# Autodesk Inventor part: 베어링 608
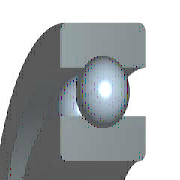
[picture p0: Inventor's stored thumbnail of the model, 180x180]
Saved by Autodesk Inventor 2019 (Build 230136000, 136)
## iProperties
IsCustomPart: 1
Created: 2012-02
Part Number: 베어링 608
Material: 강철, 연강
Description: 깊은 그루브 볼 베어링
Document SubType Name: Modeling
Standard: KS B 2023
Designer: mduedu
Standards Organization: KS
Language: ko-KR
Size Designation: 608 - 8 x 22 x 7
Categories: <MemberInstance><Categories><Category DisplayName="샤프트 부품" InternalName="7f7aeb1f-a693-4053-b835-cee3144e0d98" Mnemonic="SHFT"><Category DisplayName="베어링" Inter
Density: 1 g/cm^3
Appearance: 노란색
Author: mduedu
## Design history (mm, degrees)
sketch "스케치" dims "d0" = 3.64 (= -0.26 x WD + 0.26 x BD)
  geometry: L1 (1.68, 7.5)-(5.32, 7.5); L2 (3.5, 7.5)-(3.5, 5.68); L3 (3.5, 7.5)-(3.5, 9.32); L4 (2.148, 6.282)-(0, 6.282); L5 (0, 4)-(7, 4); L6 (2.148, 8.718)-(0, 8.718); L7 (0, 11)-(7, 11); L8 (7, 4)-(7, 6.282); L9 (4.852, 6.282)-(7, 6.282); L10 (4.852, 8.718)-(7, 8.718); L11 (7, 11)-(7, 8.718); L12 (-1.4, 0)-(8.4, 0) reference; L13 (0, -0.3)-(0, 5.3) reference
  constraints: 22 end point, 4 point on line, 2 collinear, 2 perpendicular, 2 symmetric about line, 1 midpoint, 1 parallel, 14 other
  dimensions: "d9" = 8 diameter of L5 L12 (= WD); "d11" = 22 diameter of L7 L12 (= BD); "d12" = 7 distance between parallel lines of L8 L13 (= KB); "d13" = 12.564 diameter of L9 L12 (= 0.326 x BD + 0.674 x WD)
revolve "본체" stored, may be unused: angle "d6" = 90 deg
revolve "볼" stored, may be unused: angle "d7" = 90 deg
pattern_circular "IDS_ARRAYBALL[SIMPL:T]" dims angle "d3" = 360 deg
body "Solid1"
fillet "모깎기1" dims "d1" = 0.3 (= KRS)
other parameters: "WD" = 8 [user parameter; used in 5 equation terms], "BD" = 22 [user parameter; used in 5 equation terms], "KB" = 7 [user parameter; used in 1 equation term], "KRS" = 0.3 [user parameter; used in 1 equation term], "d4" = 0, "d5" = 0, "d8" = 0, "d14" = 0, "d15" = 0, "BBA" = 0 [user parameter], "BC0" = 1370000 [user parameter], "BC" = 3250000 [user parameter], "BR" = 11 (= 0.5 x BD) [user parameter], "WR" = 4 (= 0.5 x WD) [user parameter]
